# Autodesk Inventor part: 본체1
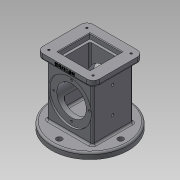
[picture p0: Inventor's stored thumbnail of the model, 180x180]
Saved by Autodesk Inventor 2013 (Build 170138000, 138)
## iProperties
Created: 2018-10
Part Number: 본체1
Material: 일반
Document SubType Name: Modeling
Designer: Administrator
Density: 1 g/cm^3
Author: Administrator
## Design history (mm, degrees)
sketch "스케치1"
  geometry: C1 r 62.5 at (0, 0); 1 further point
  constraints: 1 centre point, 1 coincident
  dimensions: "d0" = 125 diameter of C1
extrude "돌출1" new body sketch "스케치1" distance "d1" = 10; taper "d2" = 0 deg
sketch "스케치2"
  geometry: L1 (37, 33)-(-37, 33); L2 (-37, 33)-(-37, -33); L3 (-37, -33)-(37, -33); L4 (37, -33)-(37, 33); L5 (37, 33)-(-37, -33); L6 (-37, 33)-(37, -33); C1 r 62.5 at (0, 0) reference
  constraints: 12 end point, 2 midpoint, 2 parallel, 1 horizontal, 1 perpendicular
  dimensions: "d3" = 74 distance between parallel lines of L4 L2; "d5" = 66 distance between parallel lines of L3 L1
extrude "돌출2" join sketch "스케치2" distance "d6" = 88; taper "d7" = 0 deg
sketch "스케치3"
  geometry: L1 (-25.5, -10)-(99.5, -10) reference; C1 r 35 at (37, 44); 1 further point
  constraints: 1 centre point, 1 vertical alignment
  dimensions: "d8" = 70 diameter of C1; "d9" = 54 distance from line of L1 C1.centre
extrude "돌출3" cut sketch "스케치3" distance "d10" = 3; taper "d11" = 0 deg
sketch "스케치4"
  geometry: L1 (46, -41)-(-46, -41); L2 (-46, -41)-(-46, 41); L3 (-46, 41)-(46, 41); L4 (46, 41)-(46, -41); L5 (46, -41)-(-46, 41); L6 (-46, -41)-(46, 41); 1 further point
  constraints: 12 end point, 2 midpoint, 2 parallel, 1 horizontal, 1 perpendicular
  dimensions: "d12" = 92 distance between parallel lines of L4 L2; "d14" = 82 distance between parallel lines of L1 L3
extrude "돌출4" join sketch "스케치4" distance "d15" = 10; taper "d16" = 0 deg
sketch "스케치5"
  geometry: L1 (26, 26)-(-26, 26); L2 (-26, 26)-(-26, -26); L3 (-26, -26)-(26, -26); L4 (26, -26)-(26, 26); L5 (26, 26)-(-26, -26); L6 (-26, 26)-(26, -26); 1 further point
  constraints: 12 end point, 2 midpoint, 2 parallel, 1 horizontal, 1 perpendicular
  dimensions: "d17" = 52 distance of L3.end L2.end; "d18" = 52 distance of L2.end L1.end
extrude "돌출5" cut sketch "스케치5" distance "d19" = 8; taper "d20" = 0 deg
sketch "스케치6"
  geometry: L1 (22, 22)-(-22, 22); L2 (-22, 22)-(-22, -22); L3 (-22, -22)-(22, -22); L4 (22, -22)-(22, 22); L5 (22, 22)-(-22, -22); L6 (-22, 22)-(22, -22); 1 further point
  constraints: 12 end point, 2 midpoint, 2 parallel, 1 horizontal, 1 perpendicular
  dimensions: "d21" = 44 distance of L3.end L2.end; "d22" = 44 distance of L2.end L1.end
extrude "돌출6" cut sketch "스케치6" distance "d23" = 74; taper "d24" = 0 deg
sketch "스케치7"
  geometry: C1 r 35 at (0, 0) reference; C2 r 24 at (0, 0); 1 further point
  constraints: 1 centre point, 1 coincident
  dimensions: "d25" = 48 diameter of C2
extrude "돌출7" cut sketch "스케치7" stored distance "d26" = 74; taper "d27" = 0 deg
fillet "모깎기1" dims "d28" = 10
sketch "스케치8"
  geometry: C1 r 24 at (0, 0) reference; 2 further points
  constraints: 1 vertical alignment
  dimensions: "d29" = 29 distance of C1.centre point (0, 29)
hole "구멍1" sketch "스케치8" at (0, 29) diameter "d30" = 3.242; stored, may be unused: countersink angle "d34" = 90 deg, drill point angle "d36" = 118 deg; dims "d31" = 4, "d32" = 4, "d33" = 2, "d35" = 6
sketch "스케치9"
  geometry: L1 (10, -29.5)-(10, 95.5) reference; 2 further points
  constraints: 1 horizontal alignment
  dimensions: "d42" = 37 distance from line of L1 point (-27, 33)
hole "구멍2" sketch "스케치9" at (-27, 33) diameter "d43" = 4.134; stored, may be unused: countersink angle "d47" = 90 deg, drill point angle "d49" = 118 deg; dims "d44" = 4, "d45" = 4, "d46" = 2, "d48" = 6
sketch "스케치10"
  geometry: A1 r 10 centre (-36, 31) between (-36, 41) and (-46, 31) reference; A2 r 10 centre (-36, -31) between (-46, -31) and (-36, -41) reference; A3 r 10 centre (36, -31) between (36, -41) and (46, -31) reference; A4 r 10 centre (36, 31) between (46, 31) and (36, 41) reference; 1 further point
hole "구멍3" sketch "스케치10" at (36, 31), (-36, 31), (-36, -31), (36, -31) diameter "d53" = 3.242; stored, may be unused: countersink angle "d57" = 90 deg, drill point angle "d59" = 118 deg; dims "d54" = 4, "d55" = 4, "d56" = 2, "d58" = 6
sketch "스케치11"
  geometry: L1 (0, 0)-(0, 18); L2 (0, 18)-(-24.826, 18); L3 (-62.5, 0)-(62.5, 0) reference; L4 (-24.826, 18)-(-28, 0)
  constraints: 6 end point, 1 perpendicular, 1 point on line, 1 vertical
  dimensions: "d60" = 18 distance between parallel lines of L3 L2; "d61" = 80 deg angle of L3 L4; "d62" = 56 diameter of L4.end L1
revolve "회전1" sketch "스케치11" stored, may be unused: angle "d63" = 90 deg
sketch "스케치12"
  geometry: C1 r 62.5 at (0, 0) reference; C2 r 4.5 at (0, 50)
  constraints: 1 centre point, 1 vertical alignment
  dimensions: "d64" = 9 diameter of C2; "d65" = 50 distance of C1.centre C2.centre
extrude "돌출8" cut sketch "스케치12" stored distance "d66" = 74; taper "d67" = 0 deg
node "작업 평면1"
sketch "스케치13"
  geometry: L1 (-46, 108)-(-46, 98) reference; L2 (-36, 108)-(36, 108) reference; 2 further points
  constraints: 1 other
  dimensions: "d71" = 46 distance from line of L1 point (0, 104); "d72" = 4 distance from line of L2 point (0, 104)
feature "엠보싱1" sketch "스케치13" dims "d73" = 0.5, "d74" = 0
chamfer "모따기1" distance "d75" = 1; stored, may be unused: second distance "d76" = 2, angle "d77" = 45 deg
fillet "모깎기2" dims "d78" = 3
fillet "모깎기3" dims "d79" = 3
fillet "모깎기4" dims "d80" = 3
fillet "모깎기5" dims "d81" = 3
fillet "모깎기6" dims "d82" = 3
fillet "모깎기7" dims "d83" = 3
node "솔리드1"
mirror "대칭1"
pattern_circular "원형 패턴1" dims angle "d38" = 360 deg
mirror "대칭2"
pattern_linear "직사각형 패턴1" dims "d52" = 43
pattern_circular "원형 패턴2" dims angle "d69" = 360 deg
